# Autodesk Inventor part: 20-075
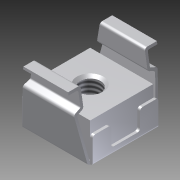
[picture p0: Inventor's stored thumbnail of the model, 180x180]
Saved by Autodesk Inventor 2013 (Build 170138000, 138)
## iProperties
Created: 2004-11
Part Number: 20-075
Description: CLIP NUT, M5 (#10-32)
Document SubType Name: Modeling
Designer: Autodesk, Inc.
Manufacturer: Standard
Standards Organization: Custom
Catalog Web Link: http://www.parker.com/ead/cm1.asp?cmid=809
Vendor: PARKER IPS
Mass: 1.10867 g
Surface Area: 14.9796 cm^2
Volume: 1.10867 cm^3
Density: 1 g/cm^3
Material: Allgemein
CAGE: 1LJX3
Dept. ID: Product Design
Description #2: ---
Finish #1: ---
Finish #2: ---
Material ID: ---
Project Number: ---
Description: Clip Nut
Order Number: 20-075
Selection: Clip Nut
Supplier: Parker Hannifin Corp., Industrial Profile Systems Div.
Author: Autodesk, Inc.
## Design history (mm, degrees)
derived "20-07X Clip Nut.ipt"
body "Solid1"
tag "TaggingFeature2"
feature "Solid1::20-07X Clip Nut.ipt" dims "ScaleForDerivedMember" = 10
